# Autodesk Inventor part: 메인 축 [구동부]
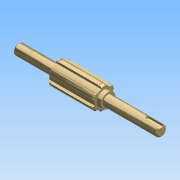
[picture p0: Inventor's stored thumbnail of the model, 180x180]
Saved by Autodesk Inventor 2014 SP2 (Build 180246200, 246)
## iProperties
Created: 2015-11
Part Number: 메인 축 [구동부]
Document SubType Name: 모델링
Designer: mdu
Mass: 168.566 g
Surface Area: 72.5104 cm^2
Volume: 21.4461 cm^3
Density: 7.86 g/cm^3
Material: 강철, 연강
Appearance: 강철
변환 표준: STEP AP214IS
파일 이름: C:\Users\SeoGD\Desktop\?쒗뿕\硫붿씤 異?.stp
전처리기: Build: 253, Release: 2010 SP1 - Date: Wed 07/29/2009
전송 단위: 밀리미터
불확실성: 0.01
Author: mdu
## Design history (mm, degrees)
sketch "스케치1"
  geometry: L1 (-69.5, 0)-(69.5, 0); L2 (69.5, 0)-(69.5, 5); L3 (69.5, 5)-(55.5, 5); L4 (55.5, 5)-(55.5, 4.8); L5 (55.5, 4.8)-(54.35, 4.8); L6 (54.35, 4.8)-(54.35, 5); L7 (54.35, 5)-(30.5, 5); L8 (30.5, 5)-(30.5, 9); L9 (30.5, 9)-(-13.5, 9); L10 (-13.5, 9)-(-13.5, 7); L11 (-13.5, 7)-(-17.5, 7); L12 (-17.5, 7)-(-17.5, 5); L13 (-17.5, 5)-(-69.5, 5); L14 (-69.5, 5)-(-69.5, 0); 2 further points
  constraints: 28 end point, 9 parallel, 4 collinear, 2 perpendicular, 1 coincident, 1 horizontal, 1 midpoint
  dimensions: "d2" = 1.15 distance between parallel lines of L6 L4; "d3" = 10 diameter of L3 L1; "d4" = 9.6 diameter of L5 L1; "d6" = 44 distance between parallel lines of L10 L8; "d7" = 4 distance between parallel lines of L12 L10; "d8" = 14 diameter of L11 L1; "d9" = 18 diameter of L9 L1; "d33" = 52 distance from line of L12.end L14; "d37" = 39 distance between parallel lines of L8 L2; "d38" = 14 distance between parallel lines of L2 L4
revolve "회전1" sketch "스케치1" stored, may be unused: angle "d10" = 90 deg
sketch "스케치2"
  geometry: L1 (2.5, 10.712)-(2.5, 8.646); L2 (-2.5, 10.712)-(-2.5, 8.646); A1 r 9 centre (0, 0) between (2.5, 8.646) and (-2.5, 8.646) reference; A2 r 11 centre (0, 0) between (2.5, 10.712) and (-2.5, 10.712); 1 further point
  constraints: 4 end point, 4 point on circle, 2 parallel, 1 centre point, 1 coincident, 1 vertical
  dimensions: "d11" = 22 diameter of A2; "d12" = 5 distance between parallel lines of L1 L2
extrude "돌출1" join sketch "스케치2" stored distance "d13" = 10; taper "d14" = 0 deg
chamfer "모따기1" distance "d15" = 1; stored, may be unused: second distance "d16" = 2, angle "d17" = 45 deg
node "작업 평면1"
node "작업 평면2"
sketch "스케치3"
  geometry: L1 (2.5, 10.712)-(2.5, 10.198); L2 (-2.5, 10.712)-(-2.5, 10.198); A1 r 11 centre (0, 0) between (2.5, 10.712) and (-2.5, 10.712) reference; A2 r 10.5 centre (0, 0) between (2.5, 10.198) and (-2.5, 10.198); 1 further point
  constraints: 4 end point, 2 point on circle, 1 centre point, 1 coincident, 1 parallel, 1 vertical
  dimensions: "d19" = 21 diameter of A2
extrude "돌출2" cut sketch "스케치3" distance "d20" = 1.35; taper "d21" = 0 deg
node "작업 평면3"
sketch "스케치4"
  geometry: L1 (-26, -5)-(-26, 5) reference; L2 (-26, 1.5)-(-12.5, 1.5); L3 (-12.5, -1.5)-(-26, -1.5); A1 r 1.5 centre (-12.5, 0) between (-12.5, -1.5) and (-12.5, 1.5); 2 further points
  constraints: 4 end point, 2 perpendicular, 2 point on circle, 2 point on line, 2 tangent, 1 centre point, 1 horizontal alignment, 1 midpoint
  dimensions: "d25" = 3 distance between parallel lines of L3 L2; "d26" = 15 dimension on A1 L1
extrude "돌출3" cut sketch "스케치4" distance "d27" = 1.8; taper "d28" = 0 deg
chamfer "모따기2" distance "d29" = 1; stored, may be unused: second distance "d30" = 2, angle "d31" = 45 deg
node "솔리드1"
node "솔리드 본체"
node "곡면 본체"
mirror "대칭1"
pattern_circular "원형 패턴1" dims "d23" = 360 deg
node "솔리드2"
other parameters: "d18" = -1.65
